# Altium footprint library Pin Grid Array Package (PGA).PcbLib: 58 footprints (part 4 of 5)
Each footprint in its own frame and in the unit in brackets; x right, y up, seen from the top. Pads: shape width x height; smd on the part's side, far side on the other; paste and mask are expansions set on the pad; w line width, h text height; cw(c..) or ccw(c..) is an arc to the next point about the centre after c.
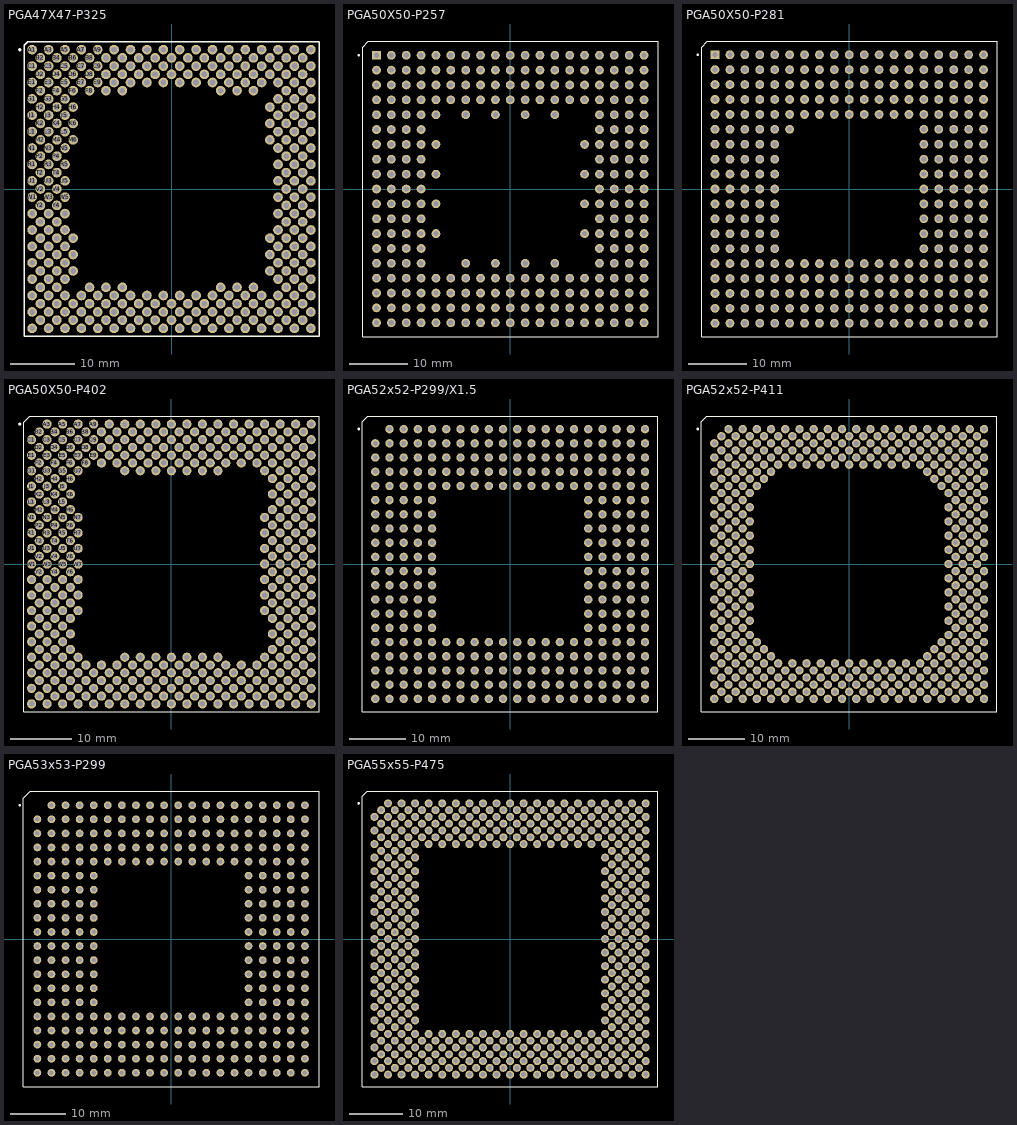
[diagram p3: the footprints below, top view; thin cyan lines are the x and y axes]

## PGA47X47-P325 [mm]
pads (325):
  round 1.5 hole 0.9: A1(-21.59,21.59) A3(-19.05,21.59) A5(-16.51,21.59) A7(-13.97,21.59) A9(-11.43,21.59) A11(-8.89,21.59) A13(-6.35,21.59) A15(-3.81,21.59) A17(-1.27,21.59) A19(1.27,21.59) A21(3.81,21.59) A23(6.35,21.59) A25(8.89,21.59) A27(11.43,21.59) A29(13.97,21.59) A31(16.51,21.59) A33(19.05,21.59) A35(21.59,21.59) AA1(-21.59,-3.81) AA3(-19.05,-3.81) AA5(-16.51,-3.81) AA31(16.51,-3.81) AA33(19.05,-3.81) AA35(21.59,-3.81) AB2(-20.32,-5.08) AB4(-17.78,-5.08) AB32(17.78,-5.08) AB34(20.32,-5.08) AC1(-21.59,-6.35) AC3(-19.05,-6.35) AC5(-16.51,-6.35) AC31(16.51,-6.35) AC33(19.05,-6.35) AC35(21.59,-6.35) AD2(-20.32,-7.62) AD4(-17.78,-7.62) AD6(-15.24,-7.62) AD30(15.24,-7.62) AD32(17.78,-7.62) AD34(20.32,-7.62) AE1(-21.59,-8.89) AE3(-19.05,-8.89) AE5(-16.51,-8.89) AE31(16.51,-8.89) AE33(19.05,-8.89) AE35(21.59,-8.89) AF2(-20.32,-10.16) AF4(-17.78,-10.16) AF6(-15.24,-10.16) AF30(15.24,-10.16) AF32(17.78,-10.16) AF34(20.32,-10.16) AG1(-21.59,-11.43) AG3(-19.05,-11.43) AG5(-16.51,-11.43) AG31(16.51,-11.43) AG33(19.05,-11.43) AG35(21.59,-11.43) AH2(-20.32,-12.7) AH4(-17.78,-12.7) AH6(-15.24,-12.7) AH30(15.24,-12.7) AH32(17.78,-12.7) AH34(20.32,-12.7) AJ1(-21.59,-13.97) AJ3(-19.05,-13.97) AJ5(-16.51,-13.97) AJ31(16.51,-13.97) AJ33(19.05,-13.97) AJ35(21.59,-13.97) AK2(-20.32,-15.24) AK4(-17.78,-15.24) AK8(-12.7,-15.24) AK10(-10.16,-15.24) AK12(-7.62,-15.24) AK24(7.62,-15.24) AK26(10.16,-15.24) AK28(12.7,-15.24) AK32(17.78,-15.24) AK34(20.32,-15.24) AL1(-21.59,-16.51) AL3(-19.05,-16.51) AL5(-16.51,-16.51) AL7(-13.97,-16.51) AL9(-11.43,-16.51) AL11(-8.89,-16.51) AL13(-6.35,-16.51) AL15(-3.81,-16.51) AL17(-1.27,-16.51) AL19(1.27,-16.51) AL21(3.81,-16.51) AL23(6.35,-16.51) AL25(8.89,-16.51) AL27(11.43,-16.51) AL29(13.97,-16.51) AL31(16.51,-16.51) AL33(19.05,-16.51) AL35(21.59,-16.51) AM2(-20.32,-17.78) AM4(-17.78,-17.78) AM6(-15.24,-17.78) AM8(-12.7,-17.78) AM10(-10.16,-17.78) AM12(-7.62,-17.78) AM14(-5.08,-17.78) AM16(-2.54,-17.78) AM18(0,-17.78) AM20(2.54,-17.78) AM22(5.08,-17.78) AM24(7.62,-17.78) AM26(10.16,-17.78) AM28(12.7,-17.78) AM30(15.24,-17.78) AM32(17.78,-17.78) AM34(20.32,-17.78) AN1(-21.59,-19.05) AN3(-19.05,-19.05) AN5(-16.51,-19.05) AN7(-13.97,-19.05) AN9(-11.43,-19.05) AN11(-8.89,-19.05) AN13(-6.35,-19.05) AN15(-3.81,-19.05) AN17(-1.27,-19.05) AN19(1.27,-19.05) AN21(3.81,-19.05) AN23(6.35,-19.05) AN25(8.89,-19.05) AN27(11.43,-19.05) AN29(13.97,-19.05) AN31(16.51,-19.05) AN33(19.05,-19.05) AN35(21.59,-19.05) AP2(-20.32,-20.32) AP4(-17.78,-20.32) AP6(-15.24,-20.32) AP8(-12.7,-20.32) AP10(-10.16,-20.32) AP12(-7.62,-20.32) AP14(-5.08,-20.32) AP16(-2.54,-20.32) AP18(0,-20.32) AP20(2.54,-20.32) AP22(5.08,-20.32) AP24(7.62,-20.32) AP26(10.16,-20.32) AP28(12.7,-20.32) AP30(15.24,-20.32) AP32(17.78,-20.32) AP34(20.32,-20.32) AR1(-21.59,-21.59) AR3(-19.05,-21.59) AR5(-16.51,-21.59) AR7(-13.97,-21.59) AR9(-11.43,-21.59) AR11(-8.89,-21.59) AR13(-6.35,-21.59) AR15(-3.81,-21.59) AR17(-1.27,-21.59) AR19(1.27,-21.59) AR21(3.81,-21.59) AR23(6.35,-21.59) AR25(8.89,-21.59) AR27(11.43,-21.59) AR29(13.97,-21.59) AR31(16.51,-21.59) AR33(19.05,-21.59) AR35(21.59,-21.59) B2(-20.32,20.32) B4(-17.78,20.32) B6(-15.24,20.32) B8(-12.7,20.32) B10(-10.16,20.32) B12(-7.62,20.32) B14(-5.08,20.32) B16(-2.54,20.32) B18(0,20.32) B20(2.54,20.32) B22(5.08,20.32) B24(7.62,20.32) B26(10.16,20.32) B28(12.7,20.32) B30(15.24,20.32) B32(17.78,20.32) B34(20.32,20.32) C1(-21.59,19.05) C3(-19.05,19.05) C5(-16.51,19.05) C7(-13.97,19.05) C9(-11.43,19.05) C11(-8.89,19.05) C13(-6.35,19.05) C15(-3.81,19.05) C17(-1.27,19.05) C19(1.27,19.05) C21(3.81,19.05) C23(6.35,19.05) C25(8.89,19.05) C27(11.43,19.05) C29(13.97,19.05) C31(16.51,19.05) C33(19.05,19.05) C35(21.59,19.05) D2(-20.32,17.78) D4(-17.78,17.78) D6(-15.24,17.78) D8(-12.7,17.78) D10(-10.16,17.78) D12(-7.62,17.78) D14(-5.08,17.78) D16(-2.54,17.78) D18(0,17.78) D20(2.54,17.78) D22(5.08,17.78) D24(7.62,17.78) D26(10.16,17.78) D28(12.7,17.78) D30(15.24,17.78) D32(17.78,17.78) D34(20.32,17.78) E1(-21.59,16.51) E3(-19.05,16.51) E5(-16.51,16.51) E7(-13.97,16.51) E9(-11.43,16.51) E11(-8.89,16.51) E13(-6.35,16.51) E15(-3.81,16.51) E17(-1.27,16.51) E19(1.27,16.51) E21(3.81,16.51) E23(6.35,16.51) E25(8.89,16.51) E27(11.43,16.51) E29(13.97,16.51) E31(16.51,16.51) E33(19.05,16.51) E35(21.59,16.51) F2(-20.32,15.24) F4(-17.78,15.24) F6(-15.24,15.24) F8(-12.7,15.24) F10(-10.16,15.24) F12(-7.62,15.24) F24(7.62,15.24) F26(10.16,15.24) F28(12.7,15.24) F32(17.78,15.24) F34(20.32,15.24) G1(-21.59,13.97) G3(-19.05,13.97) G5(-16.51,13.97) G31(16.51,13.97) G33(19.05,13.97) G35(21.59,13.97) H2(-20.32,12.7) H4(-17.78,12.7) H6(-15.24,12.7) H30(15.24,12.7) H32(17.78,12.7) H34(20.32,12.7) J1(-21.59,11.43) J3(-19.05,11.43) J5(-16.51,11.43) J31(16.51,11.43) J33(19.05,11.43) J35(21.59,11.43) K2(-20.32,10.16) K4(-17.78,10.16) K6(-15.24,10.16) K30(15.24,10.16) K32(17.78,10.16) K34(20.32,10.16) L1(-21.59,8.89) L3(-19.05,8.89) L5(-16.51,8.89) L31(16.51,8.89) L33(19.05,8.89) L35(21.59,8.89) M2(-20.32,7.62) M4(-17.78,7.62) M6(-15.24,7.62) M30(15.24,7.62) M32(17.78,7.62) M34(20.32,7.62) N1(-21.59,6.35) N3(-19.05,6.35) N5(-16.51,6.35) N31(16.51,6.35) N33(19.05,6.35) N35(21.59,6.35) P2(-20.32,5.08) P4(-17.78,5.08) P32(17.78,5.08) P34(20.32,5.08) R1(-21.59,3.81) R3(-19.05,3.81) R5(-16.51,3.81) R31(16.51,3.81) R33(19.05,3.81) R35(21.59,3.81) T2(-20.32,2.54) T4(-17.78,2.54) T32(17.78,2.54) T34(20.32,2.54) U1(-21.59,1.27) U3(-19.05,1.27) U5(-16.51,1.27) U31(16.51,1.27) U33(19.05,1.27) U35(21.59,1.27) V2(-20.32,0) V4(-17.78,0) V32(17.78,0) V34(20.32,0) W1(-21.59,-1.27) W3(-19.05,-1.27) W5(-16.51,-1.27) W31(16.51,-1.27) W33(19.05,-1.27) W35(21.59,-1.27) Y2(-20.32,-2.54) Y4(-17.78,-2.54) Y32(17.78,-2.54) Y34(20.32,-2.54)
Top Overlay:
  circle w0.25: c-23.51,21.59 r0.125
  lines w0.2: -22.86,-22.86 -22.86,22.286 -22.286,22.86 22.86,22.86 22.86,-22.86 -22.86,-22.86

## PGA50X50-P257 [mm]
pads (257):
  rect 1.5x1.5 hole 0.9: A1(-22.86,22.86)
  round 1.5 hole 0.9: A2(-20.32,22.86) A3(-17.78,22.86) A4(-15.24,22.86) A5(-12.7,22.86) A6(-10.16,22.86) A7(-7.62,22.86) A8(-5.08,22.86) A9(-2.54,22.86) A10(0,22.86) A11(2.54,22.86) A12(5.08,22.86) A13(7.62,22.86) A14(10.16,22.86) A15(12.7,22.86) A16(15.24,22.86) A17(17.78,22.86) A18(20.32,22.86) A19(22.86,22.86) B1(-22.86,20.32) B2(-20.32,20.32) B3(-17.78,20.32) B4(-15.24,20.32) B5(-12.7,20.32) B6(-10.16,20.32) B7(-7.62,20.32) B8(-5.08,20.32) B9(-2.54,20.32) B10(0,20.32) B11(2.54,20.32) B12(5.08,20.32) B13(7.62,20.32) B14(10.16,20.32) B15(12.7,20.32) B16(15.24,20.32) B17(17.78,20.32) B18(20.32,20.32) B19(22.86,20.32) C1(-22.86,17.78) C2(-20.32,17.78) C3(-17.78,17.78) C4(-15.24,17.78) C5(-12.7,17.78) C6(-10.16,17.78) C7(-7.62,17.78) C8(-5.08,17.78) C9(-2.54,17.78) C10(0,17.78) C11(2.54,17.78) C12(5.08,17.78) C13(7.62,17.78) C14(10.16,17.78) C15(12.7,17.78) C16(15.24,17.78) C17(17.78,17.78) C18(20.32,17.78) C19(22.86,17.78) D1(-22.86,15.24) D2(-20.32,15.24) D3(-17.78,15.24) D4(-15.24,15.24) D5(-12.7,15.24) D6(-10.16,15.24) D7(-7.62,15.24) D8(-5.08,15.24) D9(-2.54,15.24) D10(0,15.24) D11(2.54,15.24) D12(5.08,15.24) D13(7.62,15.24) D14(10.16,15.24) D15(12.7,15.24) D16(15.24,15.24) D17(17.78,15.24) D18(20.32,15.24) D19(22.86,15.24) E1(-22.86,12.7) E2(-20.32,12.7) E3(-17.78,12.7) E4(-15.24,12.7) E5(-12.7,12.7) E7(-7.62,12.7) E9(-2.54,12.7) E11(2.54,12.7) E13(7.62,12.7) E16(15.24,12.7) E17(17.78,12.7) E18(20.32,12.7) E19(22.86,12.7) F1(-22.86,10.16) F2(-20.32,10.16) F3(-17.78,10.16) F4(-15.24,10.16) F16(15.24,10.16) F17(17.78,10.16) F18(20.32,10.16) F19(22.86,10.16) G1(-22.86,7.62) G2(-20.32,7.62) G3(-17.78,7.62) G4(-15.24,7.62) G5(-12.7,7.62) G15(12.7,7.62) G16(15.24,7.62) G17(17.78,7.62) G18(20.32,7.62) G19(22.86,7.62) H1(-22.86,5.08) H2(-20.32,5.08) H3(-17.78,5.08) H4(-15.24,5.08) H16(15.24,5.08) H17(17.78,5.08) H18(20.32,5.08) H19(22.86,5.08) J1(-22.86,2.54) J2(-20.32,2.54) J3(-17.78,2.54) J4(-15.24,2.54) J5(-12.7,2.54) J15(12.7,2.54) J16(15.24,2.54) J17(17.78,2.54) J18(20.32,2.54) J19(22.86,2.54) K1(-22.86,0) K2(-20.32,0) K3(-17.78,0) K4(-15.24,0) K16(15.24,0) K17(17.78,0) K18(20.32,0) K19(22.86,0) L1(-22.86,-2.54) L2(-20.32,-2.54) L3(-17.78,-2.54) L4(-15.24,-2.54) L5(-12.7,-2.54) L15(12.7,-2.54) L16(15.24,-2.54) L17(17.78,-2.54) L18(20.32,-2.54) L19(22.86,-2.54) M1(-22.86,-5.08) M2(-20.32,-5.08) M3(-17.78,-5.08) M4(-15.24,-5.08) M16(15.24,-5.08) M17(17.78,-5.08) M18(20.32,-5.08) M19(22.86,-5.08) N1(-22.86,-7.62) N2(-20.32,-7.62) N3(-17.78,-7.62) N4(-15.24,-7.62) N5(-12.7,-7.62) N15(12.7,-7.62) N16(15.24,-7.62) N17(17.78,-7.62) N18(20.32,-7.62) N19(22.86,-7.62) P1(-22.86,-10.16) P2(-20.32,-10.16) P3(-17.78,-10.16) P4(-15.24,-10.16) P16(15.24,-10.16) P17(17.78,-10.16) P18(20.32,-10.16) P19(22.86,-10.16) R1(-22.86,-12.7) R2(-20.32,-12.7) R3(-17.78,-12.7) R4(-15.24,-12.7) R7(-7.62,-12.7) R9(-2.54,-12.7) R11(2.54,-12.7) R13(7.62,-12.7) R16(15.24,-12.7) R17(17.78,-12.7) R18(20.32,-12.7) R19(22.86,-12.7) T1(-22.86,-15.24) T2(-20.32,-15.24) T3(-17.78,-15.24) T4(-15.24,-15.24) T5(-12.7,-15.24) T6(-10.16,-15.24) T7(-7.62,-15.24) T8(-5.08,-15.24) T9(-2.54,-15.24) T10(0,-15.24) T11(2.54,-15.24) T12(5.08,-15.24) T13(7.62,-15.24) T14(10.16,-15.24) T15(12.7,-15.24) T16(15.24,-15.24) T17(17.78,-15.24) T18(20.32,-15.24) T19(22.86,-15.24) V1(-22.86,-17.78) V2(-20.32,-17.78) V3(-17.78,-17.78) V4(-15.24,-17.78) V5(-12.7,-17.78) V6(-10.16,-17.78) V7(-7.62,-17.78) V8(-5.08,-17.78) V9(-2.54,-17.78) V10(0,-17.78) V11(2.54,-17.78) V12(5.08,-17.78) V13(7.62,-17.78) V14(10.16,-17.78) V15(12.7,-17.78) V16(15.24,-17.78) V17(17.78,-17.78) V18(20.32,-17.78) V19(22.86,-17.78) X1(-22.86,-20.32) X2(-20.32,-20.32) X3(-17.78,-20.32) X4(-15.24,-20.32) X5(-12.7,-20.32) X6(-10.16,-20.32) X7(-7.62,-20.32) X8(-5.08,-20.32) X9(-2.54,-20.32) X10(0,-20.32) X11(2.54,-20.32) X12(5.08,-20.32) X13(7.62,-20.32) X14(10.16,-20.32) X15(12.7,-20.32) X16(15.24,-20.32) X17(17.78,-20.32) X18(20.32,-20.32) X19(22.86,-20.32) Y1(-22.86,-22.86) Y2(-20.32,-22.86) Y3(-17.78,-22.86) Y4(-15.24,-22.86) Y5(-12.7,-22.86) Y6(-10.16,-22.86) Y7(-7.62,-22.86) Y8(-5.08,-22.86) Y9(-2.54,-22.86) Y10(0,-22.86) Y11(2.54,-22.86) Y12(5.08,-22.86) Y13(7.62,-22.86) Y14(10.16,-22.86) Y15(12.7,-22.86) Y16(15.24,-22.86) Y17(17.78,-22.86) Y18(20.32,-22.86) Y19(22.86,-22.86)
Top Overlay:
  circle w0.25: c-25.9,22.86 r0.125
  lines w0.2: -25.25,-25.25 -25.25,24.25 -24.25,25.25 25.25,25.25 25.25,-25.25 -25.25,-25.25

## PGA50X50-P281 [mm]
pads (281):
  rect 1.5x1.5 hole 0.9: A1(-22.86,22.86)
  round 1.5 hole 0.9: A2(-20.32,22.86) A3(-17.78,22.86) A4(-15.24,22.86) A5(-12.7,22.86) A6(-10.16,22.86) A7(-7.62,22.86) A8(-5.08,22.86) A9(-2.54,22.86) A10(0,22.86) A11(2.54,22.86) A12(5.08,22.86) A13(7.62,22.86) A14(10.16,22.86) A15(12.7,22.86) A16(15.24,22.86) A17(17.78,22.86) A18(20.32,22.86) A19(22.86,22.86) B1(-22.86,20.32) B2(-20.32,20.32) B3(-17.78,20.32) B4(-15.24,20.32) B5(-12.7,20.32) B6(-10.16,20.32) B7(-7.62,20.32) B8(-5.08,20.32) B9(-2.54,20.32) B10(0,20.32) B11(2.54,20.32) B12(5.08,20.32) B13(7.62,20.32) B14(10.16,20.32) B15(12.7,20.32) B16(15.24,20.32) B17(17.78,20.32) B18(20.32,20.32) B19(22.86,20.32) C1(-22.86,17.78) C2(-20.32,17.78) C3(-17.78,17.78) C4(-15.24,17.78) C5(-12.7,17.78) C6(-10.16,17.78) C7(-7.62,17.78) C8(-5.08,17.78) C9(-2.54,17.78) C10(0,17.78) C11(2.54,17.78) C12(5.08,17.78) C13(7.62,17.78) C14(10.16,17.78) C15(12.7,17.78) C16(15.24,17.78) C17(17.78,17.78) C18(20.32,17.78) C19(22.86,17.78) D1(-22.86,15.24) D2(-20.32,15.24) D3(-17.78,15.24) D4(-15.24,15.24) D5(-12.7,15.24) D6(-10.16,15.24) D7(-7.62,15.24) D8(-5.08,15.24) D9(-2.54,15.24) D10(0,15.24) D11(2.54,15.24) D12(5.08,15.24) D13(7.62,15.24) D14(10.16,15.24) D15(12.7,15.24) D16(15.24,15.24) D17(17.78,15.24) D18(20.32,15.24) D19(22.86,15.24) E1(-22.86,12.7) E2(-20.32,12.7) E3(-17.78,12.7) E4(-15.24,12.7) E5(-12.7,12.7) E6(-10.16,12.7) E7(-7.62,12.7) E8(-5.08,12.7) E9(-2.54,12.7) E10(0,12.7) E11(2.54,12.7) E12(5.08,12.7) E13(7.62,12.7) E14(10.16,12.7) E15(12.7,12.7) E16(15.24,12.7) E17(17.78,12.7) E18(20.32,12.7) E19(22.86,12.7) F1(-22.86,10.16) F2(-20.32,10.16) F3(-17.78,10.16) F4(-15.24,10.16) F5(-12.7,10.16) F6(-10.16,10.16) F15(12.7,10.16) F16(15.24,10.16) F17(17.78,10.16) F18(20.32,10.16) F19(22.86,10.16) G1(-22.86,7.62) G2(-20.32,7.62) G3(-17.78,7.62) G4(-15.24,7.62) G5(-12.7,7.62) G15(12.7,7.62) G16(15.24,7.62) G17(17.78,7.62) G18(20.32,7.62) G19(22.86,7.62) H1(-22.86,5.08) H2(-20.32,5.08) H3(-17.78,5.08) H4(-15.24,5.08) H5(-12.7,5.08) H15(12.7,5.08) H16(15.24,5.08) H17(17.78,5.08) H18(20.32,5.08) H19(22.86,5.08) J1(-22.86,2.54) J2(-20.32,2.54) J3(-17.78,2.54) J4(-15.24,2.54) J5(-12.7,2.54) J15(12.7,2.54) J16(15.24,2.54) J17(17.78,2.54) J18(20.32,2.54) J19(22.86,2.54) K1(-22.86,0) K2(-20.32,0) K3(-17.78,0) K4(-15.24,0) K5(-12.7,0) K15(12.7,0) K16(15.24,0) K17(17.78,0) K18(20.32,0) K19(22.86,0) L1(-22.86,-2.54) L2(-20.32,-2.54) L3(-17.78,-2.54) L4(-15.24,-2.54) L5(-12.7,-2.54) L15(12.7,-2.54) L16(15.24,-2.54) L17(17.78,-2.54) L18(20.32,-2.54) L19(22.86,-2.54) M1(-22.86,-5.08) M2(-20.32,-5.08) M3(-17.78,-5.08) M4(-15.24,-5.08) M5(-12.7,-5.08) M15(12.7,-5.08) M16(15.24,-5.08) M17(17.78,-5.08) M18(20.32,-5.08) M19(22.86,-5.08) N1(-22.86,-7.62) N2(-20.32,-7.62) N3(-17.78,-7.62) N4(-15.24,-7.62) N5(-12.7,-7.62) N15(12.7,-7.62) N16(15.24,-7.62) N17(17.78,-7.62) N18(20.32,-7.62) N19(22.86,-7.62) P1(-22.86,-10.16) P2(-20.32,-10.16) P3(-17.78,-10.16) P4(-15.24,-10.16) P5(-12.7,-10.16) P15(12.7,-10.16) P16(15.24,-10.16) P17(17.78,-10.16) P18(20.32,-10.16) P19(22.86,-10.16) R1(-22.86,-12.7) R2(-20.32,-12.7) R3(-17.78,-12.7) R4(-15.24,-12.7) R5(-12.7,-12.7) R6(-10.16,-12.7) R7(-7.62,-12.7) R8(-5.08,-12.7) R9(-2.54,-12.7) R10(0,-12.7) R11(2.54,-12.7) R12(5.08,-12.7) R13(7.62,-12.7) R14(10.16,-12.7) R15(12.7,-12.7) R16(15.24,-12.7) R17(17.78,-12.7) R18(20.32,-12.7) R19(22.86,-12.7) T1(-22.86,-15.24) T2(-20.32,-15.24) T3(-17.78,-15.24) T4(-15.24,-15.24) T5(-12.7,-15.24) T6(-10.16,-15.24) T7(-7.62,-15.24) T8(-5.08,-15.24) T9(-2.54,-15.24) T10(0,-15.24) T11(2.54,-15.24) T12(5.08,-15.24) T13(7.62,-15.24) T14(10.16,-15.24) T15(12.7,-15.24) T16(15.24,-15.24) T17(17.78,-15.24) T18(20.32,-15.24) T19(22.86,-15.24) U1(-22.86,-17.78) U2(-20.32,-17.78) U3(-17.78,-17.78) U4(-15.24,-17.78) U5(-12.7,-17.78) U6(-10.16,-17.78) U7(-7.62,-17.78) U8(-5.08,-17.78) U9(-2.54,-17.78) U10(0,-17.78) U11(2.54,-17.78) U12(5.08,-17.78) U13(7.62,-17.78) U14(10.16,-17.78) U15(12.7,-17.78) U16(15.24,-17.78) U17(17.78,-17.78) U18(20.32,-17.78) U19(22.86,-17.78) V1(-22.86,-20.32) V2(-20.32,-20.32) V3(-17.78,-20.32) V4(-15.24,-20.32) V5(-12.7,-20.32) V6(-10.16,-20.32) V7(-7.62,-20.32) V8(-5.08,-20.32) V9(-2.54,-20.32) V10(0,-20.32) V11(2.54,-20.32) V12(5.08,-20.32) V13(7.62,-20.32) V14(10.16,-20.32) V15(12.7,-20.32) V16(15.24,-20.32) V17(17.78,-20.32) V18(20.32,-20.32) V19(22.86,-20.32) W1(-22.86,-22.86) W2(-20.32,-22.86) W3(-17.78,-22.86) W4(-15.24,-22.86) W5(-12.7,-22.86) W6(-10.16,-22.86) W7(-7.62,-22.86) W8(-5.08,-22.86) W9(-2.54,-22.86) W10(0,-22.86) W11(2.54,-22.86) W12(5.08,-22.86) W13(7.62,-22.86) W14(10.16,-22.86) W15(12.7,-22.86) W16(15.24,-22.86) W17(17.78,-22.86) W18(20.32,-22.86) W19(22.86,-22.86)
Top Overlay:
  circle w0.25: c-25.8,22.86 r0.125
  lines w0.2: -25.15,-25.15 -25.15,24.15 -24.15,25.15 25.15,25.15 25.15,-25.15 -25.15,-25.15

## PGA50X50-P402 [mm]
pads (403):
  round 1.5 hole 0.9: A3(-20.32,22.86) A5(-17.78,22.86) A7(-15.24,22.86) A9(-12.7,22.86) A11(-10.16,22.86) A13(-7.62,22.86) A15(-5.08,22.86) A17(-2.54,22.86) A19(0,22.86) A21(2.54,22.86) A23(5.08,22.86) A25(7.62,22.86) A27(10.16,22.86) A29(12.7,22.86) A31(15.24,22.86) A33(17.78,22.86) A35(20.32,22.86) A37(22.86,22.86) AA1(-22.86,-2.54) AA3(-20.32,-2.54) AA5(-17.78,-2.54) AA7(-15.24,-2.54) AA31(15.24,-2.54) AA33(17.78,-2.54) AA35(20.32,-2.54) AA37(22.86,-2.54) AB2(-21.59,-3.81) AB4(-19.05,-3.81) AB6(-16.51,-3.81) AB32(16.51,-3.81) AB34(19.05,-3.81) AB36(21.59,-3.81) AC1(-22.86,-5.08) AC3(-20.32,-5.08) AC5(-17.78,-5.08) AC7(-15.24,-5.08) AC31(15.24,-5.08) AC33(17.78,-5.08) AC35(20.32,-5.08) AC37(22.86,-5.08) AD2(-21.59,-6.35) AD4(-19.05,-6.35) AD6(-16.51,-6.35) AD32(16.51,-6.35) AD34(19.05,-6.35) AD36(21.59,-6.35) AE1(-22.86,-7.62) AE3(-20.32,-7.62) AE5(-17.78,-7.62) AE7(-15.24,-7.62) AE31(15.24,-7.62) AE33(17.78,-7.62) AE35(20.32,-7.62) AE37(22.86,-7.62) AF2(-21.59,-8.89) AF4(-19.05,-8.89) AF6(-16.51,-8.89) AF32(16.51,-8.89) AF34(19.05,-8.89) AF36(21.59,-8.89) AG1(-22.86,-10.16) AG3(-20.32,-10.16) AG5(-17.78,-10.16) AG33(17.78,-10.16) AG35(20.32,-10.16) AG37(22.86,-10.16) AH2(-21.59,-11.43) AH4(-19.05,-11.43) AH6(-16.51,-11.43) AH32(16.51,-11.43) AH34(19.05,-11.43) AH36(21.59,-11.43) AJ1(-22.86,-12.7) AJ3(-20.32,-12.7) AJ5(-17.78,-12.7) AJ33(17.78,-12.7) AJ35(20.32,-12.7) AJ37(22.86,-12.7) AK2(-21.59,-13.97) AK4(-19.05,-13.97) AK6(-16.51,-13.97) AK32(16.51,-13.97) AK34(19.05,-13.97) AK36(21.59,-13.97) AL1(-22.86,-15.24) AL3(-20.32,-15.24) AL5(-17.78,-15.24) AL7(-15.24,-15.24) AL13(-7.62,-15.24) AL15(-5.08,-15.24) AL17(-2.54,-15.24) AL19(0,-15.24) AL21(2.54,-15.24) AL23(5.08,-15.24) AL25(7.62,-15.24) AL31(15.24,-15.24) AL33(17.78,-15.24) AL35(20.32,-15.24) AL37(22.86,-15.24) AM2(-21.59,-16.51) AM4(-19.05,-16.51) AM6(-16.51,-16.51) AM8(-13.97,-16.51) AM10(-11.43,-16.51) AM12(-8.89,-16.51) AM14(-6.35,-16.51) AM16(-3.81,-16.51) AM18(-1.27,-16.51) AM20(1.27,-16.51) AM22(3.81,-16.51) AM24(6.35,-16.51) AM26(8.89,-16.51) AM28(11.43,-16.51) AM30(13.97,-16.51) AM32(16.51,-16.51) AM34(19.05,-16.51) AM36(21.59,-16.51) AN1(-22.86,-17.78) AN3(-20.32,-17.78) AN5(-17.78,-17.78) AN7(-15.24,-17.78) AN9(-12.7,-17.78) AN11(-10.16,-17.78) AN13(-7.62,-17.78) AN15(-5.08,-17.78) AN17(-2.54,-17.78) AN19(0,-17.78) AN21(2.54,-17.78) AN23(5.08,-17.78) AN25(7.62,-17.78) AN27(10.16,-17.78) AN29(12.7,-17.78) AN31(15.24,-17.78) AN33(17.78,-17.78) AN35(20.32,-17.78) AN37(22.86,-17.78) AP2(-21.59,-19.05) AP4(-19.05,-19.05) AP6(-16.51,-19.05) AP8(-13.97,-19.05) AP10(-11.43,-19.05) AP12(-8.89,-19.05) AP14(-6.35,-19.05) AP16(-3.81,-19.05) AP18(-1.27,-19.05) AP20(1.27,-19.05) AP22(3.81,-19.05) AP24(6.35,-19.05) AP26(8.89,-19.05) AP28(11.43,-19.05) AP30(13.97,-19.05) AP32(16.51,-19.05) AP34(19.05,-19.05) AP36(21.59,-19.05) AR1(-22.86,-20.32) AR3(-20.32,-20.32) AR5(-17.78,-20.32) AR7(-15.24,-20.32) AR9(-12.7,-20.32) AR11(-10.16,-20.32) AR13(-7.62,-20.32) AR15(-5.08,-20.32) AR17(-2.54,-20.32) AR19(0,-20.32) AR21(2.54,-20.32) AR23(5.08,-20.32) AR25(7.62,-20.32) AR27(10.16,-20.32) AR29(12.7,-20.32) AR31(15.24,-20.32) AR33(17.78,-20.32) AR35(20.32,-20.32) AR37(22.86,-20.32) AT2(-21.59,-21.59) AT4(-19.05,-21.59) AT6(-16.51,-21.59) AT8(-13.97,-21.59) AT10(-11.43,-21.59) AT12(-8.89,-21.59) AT14(-6.35,-21.59) AT16(-3.81,-21.59) AT18(-1.27,-21.59) AT20(1.27,-21.59) AT22(3.81,-21.59) AT24(6.35,-21.59) AT26(8.89,-21.59) AT28(11.43,-21.59) AT30(13.97,-21.59) AT32(16.51,-21.59) AT34(19.05,-21.59) AT36(21.59,-21.59) AU1(-22.86,-22.86) AU3(-20.32,-22.86) AU5(-17.78,-22.86) AU7(-15.24,-22.86) AU9(-12.7,-22.86) AU11(-10.16,-22.86) AU13(-7.62,-22.86) AU15(-5.08,-22.86) AU17(-2.54,-22.86) AU19(0,-22.86) AU21(2.54,-22.86) AU23(5.08,-22.86) AU25(7.62,-22.86) AU27(10.16,-22.86) AU29(12.7,-22.86) AU31(15.24,-22.86) AU33(17.78,-22.86) AU35(20.32,-22.86) AU37(22.86,-22.86) B2(-21.59,21.59) B4(-19.05,21.59) B6(-16.51,21.59) B8(-13.97,21.59) B10(-11.43,21.59) B12(-8.89,21.59) B14(-6.35,21.59) B16(-3.81,21.59) B18(-1.27,21.59) B20(1.27,21.59) B22(3.81,21.59) B24(6.35,21.59) B26(8.89,21.59) B28(11.43,21.59) B30(13.97,21.59) B32(16.51,21.59) B34(19.05,21.59) B36(21.59,21.59) C1(-22.86,20.32) C3(-20.32,20.32) C5(-17.78,20.32) C7(-15.24,20.32) C9(-12.7,20.32) C11(-10.16,20.32) C13(-7.62,20.32) C15(-5.08,20.32) C17(-2.54,20.32) C19(0,20.32) C21(2.54,20.32) C23(5.08,20.32) C25(7.62,20.32) C27(10.16,20.32) C29(12.7,20.32) C31(15.24,20.32) C33(17.78,20.32) C35(20.32,20.32) C37(22.86,20.32) D2(-21.59,19.05) D4(-19.05,19.05) D6(-16.51,19.05) D8(-13.97,19.05) D10(-11.43,19.05) D12(-8.89,19.05) D14(-6.35,19.05) D16(-3.81,19.05) D18(-1.27,19.05) D20(1.27,19.05) D22(3.81,19.05) D24(6.35,19.05) D26(8.89,19.05) D28(11.43,19.05) D30(13.97,19.05) D32(16.51,19.05) D34(19.05,19.05) D36(21.59,19.05) E1(-22.86,17.78) E3(-20.32,17.78) E5(-17.78,17.78) E7(-15.24,17.78) E9(-12.7,17.78) E11(-10.16,17.78) E13(-7.62,17.78) E15(-5.08,17.78) E17(-2.54,17.78) E19(0,17.78) E21(2.54,17.78) E23(5.08,17.78) E25(7.62,17.78) E27(10.16,17.78) E29(12.7,17.78) E31(15.24,17.78) E33(17.78,17.78) E35(20.32,17.78) E37(22.86,17.78) F2(-21.59,16.51) F4(-19.05,16.51) F6(-16.51,16.51) F8(-13.97,16.51) F10(-11.43,16.51) F12(-8.89,16.51) F14(-6.35,16.51) F16(-3.81,16.51) F18(-1.27,16.51) F20(1.27,16.51) F22(3.81,16.51) F24(6.35,16.51) F26(8.89,16.51) F28(11.43,16.51) F30(13.97,16.51) F32(16.51,16.51) F34(19.05,16.51) F36(21.59,16.51) G1(-22.86,15.24) G3(-20.32,15.24) G5(-17.78,15.24) G7(-15.24,15.24) G13(-7.62,15.24) G15(-5.08,15.24) G17(-2.54,15.24) G19(0,15.24) G21(2.54,15.24) G23(5.08,15.24) G25(7.62,15.24) G31(15.24,15.24) G33(17.78,15.24) G35(20.32,15.24) G37(22.86,15.24) H2(-21.59,13.97) H4(-19.05,13.97) H6(-16.51,13.97) H32(16.51,13.97) H34(19.05,13.97) H36(21.59,13.97) J1(-22.86,12.7) J3(-20.32,12.7) J5(-17.78,12.7) J33(17.78,12.7) J35(20.32,12.7) J37(22.86,12.7) K2(-21.59,11.43) K4(-19.05,11.43) K6(-16.51,11.43) K32(16.51,11.43) K34(19.05,11.43) K36(21.59,11.43) L1(-22.86,10.16) L3(-20.32,10.16) L5(-17.78,10.16) L33(17.78,10.16) L35(20.32,10.16) L37(22.86,10.16) M2(-21.59,8.89) M4(-19.05,8.89) M6(-16.51,8.89) M32(16.51,8.89) M34(19.05,8.89) M36(21.59,8.89) N1(-22.86,7.62) N3(-20.32,7.62) N5(-17.78,7.62) N7(-15.24,7.62) N31(15.24,7.62) N33(17.78,7.62) N35(20.32,7.62) N37(22.86,7.62) P2(-21.59,6.35) P4(-19.05,6.35) P6(-16.51,6.35) P32(16.51,6.35) P34(19.05,6.35) P36(21.59,6.35) R1(-22.86,5.08) R3(-20.32,5.08) R5(-17.78,5.08) R7(-15.24,5.08) R31(15.24,5.08) R33(17.78,5.08) R35(20.32,5.08) R37(22.86,5.08) T2(-21.59,3.81) T4(-19.05,3.81) T6(-16.51,3.81) T32(16.51,3.81) T34(19.05,3.81) T36(21.59,3.81) U1(-22.86,2.54) U3(-20.32,2.54) U5(-17.78,2.54) U7(-15.24,2.54) U31(15.24,2.54) U33(17.78,2.54) U35(20.32,2.54) U37(22.86,2.54) V2(-21.59,1.27) V4(-19.05,1.27) V6(-16.51,1.27) V32(16.51,1.27) V34(19.05,1.27) V36(21.59,1.27) W1(-22.86,0) W3(-20.32,0) W5(-17.78,0) W7(-15.24,0) W31(15.24,0) W33(17.78,0) W35(20.32,0) W37(22.86,0) Y2(-21.59,-1.27) Y4(-19.05,-1.27) Y6(-16.51,-1.27) Y32(16.51,-1.27) Y34(19.05,-1.27) Y36(21.59,-1.27)
Top Overlay:
  circle w0.25: c-24.78,22.86 r0.125
  lines w0.2: -24.13,-24.13 24.13,-24.13 24.13,24.13 -23.13,24.13 -24.13,23.13 -24.13,-24.13

## PGA52x52-P299/X1.5 [mm]
pads (299):
  round 1.5 hole 0.9: A2(-21.59,24.13) A3(-19.05,24.13) A4(-16.51,24.13) A5(-13.97,24.13) A6(-11.43,24.13) A7(-8.89,24.13) A8(-6.35,24.13) A9(-3.81,24.13) A10(-1.27,24.13) A11(1.27,24.13) A12(3.81,24.13) A13(6.35,24.13) A14(8.89,24.13) A15(11.43,24.13) A16(13.97,24.13) A17(16.51,24.13) A18(19.05,24.13) A19(21.59,24.13) A20(24.13,24.13) B1(-24.13,21.59) B2(-21.59,21.59) B3(-19.05,21.59) B4(-16.51,21.59) B5(-13.97,21.59) B6(-11.43,21.59) B7(-8.89,21.59) B8(-6.35,21.59) B9(-3.81,21.59) B10(-1.27,21.59) B11(1.27,21.59) B12(3.81,21.59) B13(6.35,21.59) B14(8.89,21.59) B15(11.43,21.59) B16(13.97,21.59) B17(16.51,21.59) B18(19.05,21.59) B19(21.59,21.59) B20(24.13,21.59) C1(-24.13,19.05) C2(-21.59,19.05) C3(-19.05,19.05) C4(-16.51,19.05) C5(-13.97,19.05) C6(-11.43,19.05) C7(-8.89,19.05) C8(-6.35,19.05) C9(-3.81,19.05) C10(-1.27,19.05) C11(1.27,19.05) C12(3.81,19.05) C13(6.35,19.05) C14(8.89,19.05) C15(11.43,19.05) C16(13.97,19.05) C17(16.51,19.05) C18(19.05,19.05) C19(21.59,19.05) C20(24.13,19.05) D1(-24.13,16.51) D2(-21.59,16.51) D3(-19.05,16.51) D4(-16.51,16.51) D5(-13.97,16.51) D6(-11.43,16.51) D7(-8.89,16.51) D8(-6.35,16.51) D9(-3.81,16.51) D10(-1.27,16.51) D11(1.27,16.51) D12(3.81,16.51) D13(6.35,16.51) D14(8.89,16.51) D15(11.43,16.51) D16(13.97,16.51) D17(16.51,16.51) D18(19.05,16.51) D19(21.59,16.51) D20(24.13,16.51) E1(-24.13,13.97) E2(-21.59,13.97) E3(-19.05,13.97) E4(-16.51,13.97) E5(-13.97,13.97) E6(-11.43,13.97) E7(-8.89,13.97) E8(-6.35,13.97) E9(-3.81,13.97) E10(-1.27,13.97) E11(1.27,13.97) E12(3.81,13.97) E13(6.35,13.97) E14(8.89,13.97) E15(11.43,13.97) E16(13.97,13.97) E17(16.51,13.97) E18(19.05,13.97) E19(21.59,13.97) E20(24.13,13.97) F1(-24.13,11.43) F2(-21.59,11.43) F3(-19.05,11.43) F4(-16.51,11.43) F5(-13.97,11.43) F16(13.97,11.43) F17(16.51,11.43) F18(19.05,11.43) F19(21.59,11.43) F20(24.13,11.43) G1(-24.13,8.89) G2(-21.59,8.89) G3(-19.05,8.89) G4(-16.51,8.89) G5(-13.97,8.89) G16(13.97,8.89) G17(16.51,8.89) G18(19.05,8.89) G19(21.59,8.89) G20(24.13,8.89) H1(-24.13,6.35) H2(-21.59,6.35) H3(-19.05,6.35) H4(-16.51,6.35) H5(-13.97,6.35) H16(13.97,6.35) H17(16.51,6.35) H18(19.05,6.35) H19(21.59,6.35) H20(24.13,6.35) J1(-24.13,3.81) J2(-21.59,3.81) J3(-19.05,3.81) J4(-16.51,3.81) J5(-13.97,3.81) J16(13.97,3.81) J17(16.51,3.81) J18(19.05,3.81) J19(21.59,3.81) J20(24.13,3.81) K1(-24.13,1.27) K2(-21.59,1.27) K3(-19.05,1.27) K4(-16.51,1.27) K5(-13.97,1.27) K16(13.97,1.27) K17(16.51,1.27) K18(19.05,1.27) K19(21.59,1.27) K20(24.13,1.27) L1(-24.13,-1.27) L2(-21.59,-1.27) L3(-19.05,-1.27) L4(-16.51,-1.27) L5(-13.97,-1.27) L16(13.97,-1.27) L17(16.51,-1.27) L18(19.05,-1.27) L19(21.59,-1.27) L20(24.13,-1.27) M1(-24.13,-3.81) M2(-21.59,-3.81) M3(-19.05,-3.81) M4(-16.51,-3.81) M5(-13.97,-3.81) M16(13.97,-3.81) M17(16.51,-3.81) M18(19.05,-3.81) M19(21.59,-3.81) M20(24.13,-3.81) N1(-24.13,-6.35) N2(-21.59,-6.35) N3(-19.05,-6.35) N4(-16.51,-6.35) N5(-13.97,-6.35) N16(13.97,-6.35) N17(16.51,-6.35) N18(19.05,-6.35) N19(21.59,-6.35) N20(24.13,-6.35) P1(-24.13,-8.89) P2(-21.59,-8.89) P3(-19.05,-8.89) P4(-16.51,-8.89) P5(-13.97,-8.89) P16(13.97,-8.89) P17(16.51,-8.89) P18(19.05,-8.89) P19(21.59,-8.89) P20(24.13,-8.89) R1(-24.13,-11.43) R2(-21.59,-11.43) R3(-19.05,-11.43) R4(-16.51,-11.43) R5(-13.97,-11.43) R16(13.97,-11.43) R17(16.51,-11.43) R18(19.05,-11.43) R19(21.59,-11.43) R20(24.13,-11.43) T1(-24.13,-13.97) T2(-21.59,-13.97) T3(-19.05,-13.97) T4(-16.51,-13.97) T5(-13.97,-13.97) T6(-11.43,-13.97) T7(-8.89,-13.97) T8(-6.35,-13.97) T9(-3.81,-13.97) T10(-1.27,-13.97) T11(1.27,-13.97) T12(3.81,-13.97) T13(6.35,-13.97) T14(8.89,-13.97) T15(11.43,-13.97) T16(13.97,-13.97) T17(16.51,-13.97) T18(19.05,-13.97) T19(21.59,-13.97) T20(24.13,-13.97) U1(-24.13,-16.51) U2(-21.59,-16.51) U3(-19.05,-16.51) U4(-16.51,-16.51) U5(-13.97,-16.51) U6(-11.43,-16.51) U7(-8.89,-16.51) U8(-6.35,-16.51) U9(-3.81,-16.51) U10(-1.27,-16.51) U11(1.27,-16.51) U12(3.81,-16.51) U13(6.35,-16.51) U14(8.89,-16.51) U15(11.43,-16.51) U16(13.97,-16.51) U17(16.51,-16.51) U18(19.05,-16.51) U19(21.59,-16.51) U20(24.13,-16.51) V1(-24.13,-19.05) V2(-21.59,-19.05) V3(-19.05,-19.05) V4(-16.51,-19.05) V5(-13.97,-19.05) V6(-11.43,-19.05) V7(-8.89,-19.05) V8(-6.35,-19.05) V9(-3.81,-19.05) V10(-1.27,-19.05) V11(1.27,-19.05) V12(3.81,-19.05) V13(6.35,-19.05) V14(8.89,-19.05) V15(11.43,-19.05) V16(13.97,-19.05) V17(16.51,-19.05) V18(19.05,-19.05) V19(21.59,-19.05) V20(24.13,-19.05) W1(-24.13,-21.59) W2(-21.59,-21.59) W3(-19.05,-21.59) W4(-16.51,-21.59) W5(-13.97,-21.59) W6(-11.43,-21.59) W7(-8.89,-21.59) W8(-6.35,-21.59) W9(-3.81,-21.59) W10(-1.27,-21.59) W11(1.27,-21.59) W12(3.81,-21.59) W13(6.35,-21.59) W14(8.89,-21.59) W15(11.43,-21.59) W16(13.97,-21.59) W17(16.51,-21.59) W18(19.05,-21.59) W19(21.59,-21.59) W20(24.13,-21.59) Y1(-24.13,-24.13) Y2(-21.59,-24.13) Y3(-19.05,-24.13) Y4(-16.51,-24.13) Y5(-13.97,-24.13) Y6(-11.43,-24.13) Y7(-8.89,-24.13) Y8(-6.35,-24.13) Y9(-3.81,-24.13) Y10(-1.27,-24.13) Y11(1.27,-24.13) Y12(3.81,-24.13) Y13(6.35,-24.13) Y14(8.89,-24.13) Y15(11.43,-24.13) Y16(13.97,-24.13) Y17(16.51,-24.13) Y18(19.05,-24.13) Y19(21.59,-24.13) Y20(24.13,-24.13)
Top Overlay:
  circle w0.25: c-27.1,24.13 r0.125
  lines w0.2: -26.45,-26.45 26.45,-26.45 26.45,26.45 -25.45,26.45 -26.45,25.45 -26.45,-26.45

## PGA52x52-P411 [mm]
pads (411):
  round 1.5 hole 0.9: A3(-21.59,24.13) A5(-19.05,24.13) A7(-16.51,24.13) A9(-13.97,24.13) A11(-11.43,24.13) A13(-8.89,24.13) A15(-6.35,24.13) A17(-3.81,24.13) A19(-1.27,24.13) A21(1.27,24.13) A23(3.81,24.13) A25(6.35,24.13) A27(8.89,24.13) A29(11.43,24.13) A31(13.97,24.13) A33(16.51,24.13) A35(19.05,24.13) A37(21.59,24.13) A39(24.13,24.13) AA1(-24.13,-1.27) AA3(-21.59,-1.27) AA5(-19.05,-1.27) AA35(19.05,-1.27) AA37(21.59,-1.27) AA39(24.13,-1.27) AB2(-22.86,-2.54) AB4(-20.32,-2.54) AB6(-17.78,-2.54) AB34(17.78,-2.54) AB36(20.32,-2.54) AB38(22.86,-2.54) AC1(-24.13,-3.81) AC3(-21.59,-3.81) AC5(-19.05,-3.81) AC35(19.05,-3.81) AC37(21.59,-3.81) AC39(24.13,-3.81) AD2(-22.86,-5.08) AD4(-20.32,-5.08) AD6(-17.78,-5.08) AD34(17.78,-5.08) AD36(20.32,-5.08) AD38(22.86,-5.08) AE1(-24.13,-6.35) AE3(-21.59,-6.35) AE5(-19.05,-6.35) AE35(19.05,-6.35) AE37(21.59,-6.35) AE39(24.13,-6.35) AF2(-22.86,-7.62) AF4(-20.32,-7.62) AF6(-17.78,-7.62) AF34(17.78,-7.62) AF36(20.32,-7.62) AF38(22.86,-7.62) AG1(-24.13,-8.89) AG3(-21.59,-8.89) AG5(-19.05,-8.89) AG35(19.05,-8.89) AG37(21.59,-8.89) AG39(24.13,-8.89) AH2(-22.86,-10.16) AH4(-20.32,-10.16) AH6(-17.78,-10.16) AH34(17.78,-10.16) AH36(20.32,-10.16) AH38(22.86,-10.16) AJ1(-24.13,-11.43) AJ3(-21.59,-11.43) AJ5(-19.05,-11.43) AJ35(19.05,-11.43) AJ37(21.59,-11.43) AJ39(24.13,-11.43) AK2(-22.86,-12.7) AK4(-20.32,-12.7) AK6(-17.78,-12.7) AK34(17.78,-12.7) AK36(20.32,-12.7) AK38(22.86,-12.7) AL1(-24.13,-13.97) AL3(-21.59,-13.97) AL5(-19.05,-13.97) AL7(-16.51,-13.97) AL33(16.51,-13.97) AL35(19.05,-13.97) AL37(21.59,-13.97) AL39(24.13,-13.97) AM2(-22.86,-15.24) AM4(-20.32,-15.24) AM6(-17.78,-15.24) AM8(-15.24,-15.24) AM32(15.24,-15.24) AM34(17.78,-15.24) AM36(20.32,-15.24) AM38(22.86,-15.24) AN1(-24.13,-16.51) AN3(-21.59,-16.51) AN5(-19.05,-16.51) AN7(-16.51,-16.51) AN9(-13.97,-16.51) AN31(13.97,-16.51) AN33(16.51,-16.51) AN35(19.05,-16.51) AN37(21.59,-16.51) AN39(24.13,-16.51) AP2(-22.86,-17.78) AP4(-20.32,-17.78) AP6(-17.78,-17.78) AP8(-15.24,-17.78) AP10(-12.7,-17.78) AP12(-10.16,-17.78) AP14(-7.62,-17.78) AP16(-5.08,-17.78) AP18(-2.54,-17.78) AP20(0,-17.78) AP22(2.54,-17.78) AP24(5.08,-17.78) AP26(7.62,-17.78) AP28(10.16,-17.78) AP30(12.7,-17.78) AP32(15.24,-17.78) AP34(17.78,-17.78) AP36(20.32,-17.78) AP38(22.86,-17.78) AR1(-24.13,-19.05) AR3(-21.59,-19.05) AR5(-19.05,-19.05) AR7(-16.51,-19.05) AR9(-13.97,-19.05) AR11(-11.43,-19.05) AR13(-8.89,-19.05) AR15(-6.35,-19.05) AR17(-3.81,-19.05) AR19(-1.27,-19.05) AR21(1.27,-19.05) AR23(3.81,-19.05) AR25(6.35,-19.05) AR27(8.89,-19.05) AR29(11.43,-19.05) AR31(13.97,-19.05) AR33(16.51,-19.05) AR35(19.05,-19.05) AR37(21.59,-19.05) AR39(24.13,-19.05) AT2(-22.86,-20.32) AT4(-20.32,-20.32) AT6(-17.78,-20.32) AT8(-15.24,-20.32) AT10(-12.7,-20.32) AT12(-10.16,-20.32) AT14(-7.62,-20.32) AT16(-5.08,-20.32) AT18(-2.54,-20.32) AT20(0,-20.32) AT22(2.54,-20.32) AT24(5.08,-20.32) AT26(7.62,-20.32) AT28(10.16,-20.32) AT30(12.7,-20.32) AT32(15.24,-20.32) AT34(17.78,-20.32) AT36(20.32,-20.32) AT38(22.86,-20.32) AU1(-24.13,-21.59) AU3(-21.59,-21.59) AU5(-19.05,-21.59) AU7(-16.51,-21.59) AU9(-13.97,-21.59) AU11(-11.43,-21.59) AU13(-8.89,-21.59) AU15(-6.35,-21.59) AU17(-3.81,-21.59) AU19(-1.27,-21.59) AU21(1.27,-21.59) AU23(3.81,-21.59) AU25(6.35,-21.59) AU27(8.89,-21.59) AU29(11.43,-21.59) AU31(13.97,-21.59) AU33(16.51,-21.59) AU35(19.05,-21.59) AU37(21.59,-21.59) AU39(24.13,-21.59) AV2(-22.86,-22.86) AV4(-20.32,-22.86) AV6(-17.78,-22.86) AV8(-15.24,-22.86) AV10(-12.7,-22.86) AV12(-10.16,-22.86) AV14(-7.62,-22.86) AV16(-5.08,-22.86) AV18(-2.54,-22.86) AV20(0,-22.86) AV22(2.54,-22.86) AV24(5.08,-22.86) AV26(7.62,-22.86) AV28(10.16,-22.86) AV30(12.7,-22.86) AV32(15.24,-22.86) AV34(17.78,-22.86) AV36(20.32,-22.86) AV38(22.86,-22.86) AW1(-24.13,-24.13) AW3(-21.59,-24.13) AW5(-19.05,-24.13) AW7(-16.51,-24.13) AW9(-13.97,-24.13) AW11(-11.43,-24.13) AW13(-8.89,-24.13) AW15(-6.35,-24.13) AW17(-3.81,-24.13) AW19(-1.27,-24.13) AW21(1.27,-24.13) AW23(3.81,-24.13) AW25(6.35,-24.13) AW27(8.89,-24.13) AW29(11.43,-24.13) AW31(13.97,-24.13) AW33(16.51,-24.13) AW35(19.05,-24.13) AW37(21.59,-24.13) AW39(24.13,-24.13) B2(-22.86,22.86) B4(-20.32,22.86) B6(-17.78,22.86) B8(-15.24,22.86) B10(-12.7,22.86) B12(-10.16,22.86) B14(-7.62,22.86) B16(-5.08,22.86) B18(-2.54,22.86) B20(0,22.86) B22(2.54,22.86) B24(5.08,22.86) B26(7.62,22.86) B28(10.16,22.86) B30(12.7,22.86) B32(15.24,22.86) B34(17.78,22.86) B36(20.32,22.86) B38(22.86,22.86) C1(-24.13,21.59) C3(-21.59,21.59) C5(-19.05,21.59) C7(-16.51,21.59) C9(-13.97,21.59) C11(-11.43,21.59) C13(-8.89,21.59) C15(-6.35,21.59) C17(-3.81,21.59) C19(-1.27,21.59) C21(1.27,21.59) C23(3.81,21.59) C25(6.35,21.59) C27(8.89,21.59) C29(11.43,21.59) C31(13.97,21.59) C33(16.51,21.59) C35(19.05,21.59) C37(21.59,21.59) C39(24.13,21.59) D2(-22.86,20.32) D4(-20.32,20.32) D6(-17.78,20.32) D8(-15.24,20.32) D10(-12.7,20.32) D12(-10.16,20.32) D14(-7.62,20.32) D16(-5.08,20.32) D18(-2.54,20.32) D20(0,20.32) D22(2.54,20.32) D24(5.08,20.32) D26(7.62,20.32) D28(10.16,20.32) D30(12.7,20.32) D32(15.24,20.32) D34(17.78,20.32) D36(20.32,20.32) D38(22.86,20.32) E1(-24.13,19.05) E3(-21.59,19.05) E5(-19.05,19.05) E7(-16.51,19.05) E9(-13.97,19.05) E11(-11.43,19.05) E13(-8.89,19.05) E15(-6.35,19.05) E17(-3.81,19.05) E19(-1.27,19.05) E21(1.27,19.05) E23(3.81,19.05) E25(6.35,19.05) E27(8.89,19.05) E29(11.43,19.05) E31(13.97,19.05) E33(16.51,19.05) E35(19.05,19.05) E37(21.59,19.05) E39(24.13,19.05) F2(-22.86,17.78) F4(-20.32,17.78) F6(-17.78,17.78) F8(-15.24,17.78) F10(-12.7,17.78) F12(-10.16,17.78) F14(-7.62,17.78) F16(-5.08,17.78) F18(-2.54,17.78) F20(0,17.78) F22(2.54,17.78) F24(5.08,17.78) F26(7.62,17.78) F28(10.16,17.78) F30(12.7,17.78) F32(15.24,17.78) F34(17.78,17.78) F36(20.32,17.78) F38(22.86,17.78) G1(-24.13,16.51) G3(-21.59,16.51) G5(-19.05,16.51) G7(-16.51,16.51) G9(-13.97,16.51) G31(13.97,16.51) G33(16.51,16.51) G35(19.05,16.51) G37(21.59,16.51) G39(24.13,16.51) H2(-22.86,15.24) H4(-20.32,15.24) H6(-17.78,15.24) H8(-15.24,15.24) H32(15.24,15.24) H34(17.78,15.24) H36(20.32,15.24) H38(22.86,15.24) J1(-24.13,13.97) J3(-21.59,13.97) J5(-19.05,13.97) J7(-16.51,13.97) J33(16.51,13.97) J35(19.05,13.97) J37(21.59,13.97) J39(24.13,13.97) K2(-22.86,12.7) K4(-20.32,12.7) K6(-17.78,12.7) K34(17.78,12.7) K36(20.32,12.7) K38(22.86,12.7) L1(-24.13,11.43) L3(-21.59,11.43) L5(-19.05,11.43) L35(19.05,11.43) L37(21.59,11.43) L39(24.13,11.43) M2(-22.86,10.16) M4(-20.32,10.16) M6(-17.78,10.16) M34(17.78,10.16) M36(20.32,10.16) M38(22.86,10.16) N1(-24.13,8.89) N3(-21.59,8.89) N5(-19.05,8.89) N35(19.05,8.89) N37(21.59,8.89) N39(24.13,8.89) P2(-22.86,7.62) P4(-20.32,7.62) P6(-17.78,7.62) P34(17.78,7.62) P36(20.32,7.62) P38(22.86,7.62) R1(-24.13,6.35) R3(-21.59,6.35) R5(-19.05,6.35) R35(19.05,6.35) R37(21.59,6.35) R39(24.13,6.35) T2(-22.86,5.08) T4(-20.32,5.08) T6(-17.78,5.08) T34(17.78,5.08) T36(20.32,5.08) T38(22.86,5.08) U1(-24.13,3.81) U3(-21.59,3.81) U5(-19.05,3.81) U35(19.05,3.81) U37(21.59,3.81) U39(24.13,3.81) V2(-22.86,2.54) V4(-20.32,2.54) V6(-17.78,2.54) V34(17.78,2.54) V36(20.32,2.54) V38(22.86,2.54) W1(-24.13,1.27) W3(-21.59,1.27) W5(-19.05,1.27) W35(19.05,1.27) W37(21.59,1.27) W39(24.13,1.27) Y2(-22.86,0) Y4(-20.32,0) Y6(-17.78,0) Y34(17.78,0) Y36(20.32,0) Y38(22.86,0)
Top Overlay:
  circle w0.25: c-27.1,24.13 r0.125
  lines w0.2: -26.45,-26.45 -26.45,25.45 -25.45,26.45 26.45,26.45 26.45,-26.45 -26.45,-26.45

## PGA53x53-P299 [mm]
pads (299):
  round 1.4 hole 0.8: A2(-21.59,24.13) A3(-19.05,24.13) A4(-16.51,24.13) A5(-13.97,24.13) A6(-11.43,24.13) A7(-8.89,24.13) A8(-6.35,24.13) A9(-3.81,24.13) A10(-1.27,24.13) A11(1.27,24.13) A12(3.81,24.13) A13(6.35,24.13) A14(8.89,24.13) A15(11.43,24.13) A16(13.97,24.13) A17(16.51,24.13) A18(19.05,24.13) A19(21.59,24.13) A20(24.13,24.13) B1(-24.13,21.59) B2(-21.59,21.59) B3(-19.05,21.59) B4(-16.51,21.59) B5(-13.97,21.59) B6(-11.43,21.59) B7(-8.89,21.59) B8(-6.35,21.59) B9(-3.81,21.59) B10(-1.27,21.59) B11(1.27,21.59) B12(3.81,21.59) B13(6.35,21.59) B14(8.89,21.59) B15(11.43,21.59) B16(13.97,21.59) B17(16.51,21.59) B18(19.05,21.59) B19(21.59,21.59) B20(24.13,21.59) C1(-24.13,19.05) C2(-21.59,19.05) C3(-19.05,19.05) C4(-16.51,19.05) C5(-13.97,19.05) C6(-11.43,19.05) C7(-8.89,19.05) C8(-6.35,19.05) C9(-3.81,19.05) C10(-1.27,19.05) C11(1.27,19.05) C12(3.81,19.05) C13(6.35,19.05) C14(8.89,19.05) C15(11.43,19.05) C16(13.97,19.05) C17(16.51,19.05) C18(19.05,19.05) C19(21.59,19.05) C20(24.13,19.05) D1(-24.13,16.51) D2(-21.59,16.51) D3(-19.05,16.51) D4(-16.51,16.51) D5(-13.97,16.51) D6(-11.43,16.51) D7(-8.89,16.51) D8(-6.35,16.51) D9(-3.81,16.51) D10(-1.27,16.51) D11(1.27,16.51) D12(3.81,16.51) D13(6.35,16.51) D14(8.89,16.51) D15(11.43,16.51) D16(13.97,16.51) D17(16.51,16.51) D18(19.05,16.51) D19(21.59,16.51) D20(24.13,16.51) E1(-24.13,13.97) E2(-21.59,13.97) E3(-19.05,13.97) E4(-16.51,13.97) E5(-13.97,13.97) E6(-11.43,13.97) E7(-8.89,13.97) E8(-6.35,13.97) E9(-3.81,13.97) E10(-1.27,13.97) E11(1.27,13.97) E12(3.81,13.97) E13(6.35,13.97) E14(8.89,13.97) E15(11.43,13.97) E16(13.97,13.97) E17(16.51,13.97) E18(19.05,13.97) E19(21.59,13.97) E20(24.13,13.97) F1(-24.13,11.43) F2(-21.59,11.43) F3(-19.05,11.43) F4(-16.51,11.43) F5(-13.97,11.43) F16(13.97,11.43) F17(16.51,11.43) F18(19.05,11.43) F19(21.59,11.43) F20(24.13,11.43) G1(-24.13,8.89) G2(-21.59,8.89) G3(-19.05,8.89) G4(-16.51,8.89) G5(-13.97,8.89) G16(13.97,8.89) G17(16.51,8.89) G18(19.05,8.89) G19(21.59,8.89) G20(24.13,8.89) H1(-24.13,6.35) H2(-21.59,6.35) H3(-19.05,6.35) H4(-16.51,6.35) H5(-13.97,6.35) H16(13.97,6.35) H17(16.51,6.35) H18(19.05,6.35) H19(21.59,6.35) H20(24.13,6.35) J1(-24.13,3.81) J2(-21.59,3.81) J3(-19.05,3.81) J4(-16.51,3.81) J5(-13.97,3.81) J16(13.97,3.81) J17(16.51,3.81) J18(19.05,3.81) J19(21.59,3.81) J20(24.13,3.81) K1(-24.13,1.27) K2(-21.59,1.27) K3(-19.05,1.27) K4(-16.51,1.27) K5(-13.97,1.27) K16(13.97,1.27) K17(16.51,1.27) K18(19.05,1.27) K19(21.59,1.27) K20(24.13,1.27) L1(-24.13,-1.27) L2(-21.59,-1.27) L3(-19.05,-1.27) L4(-16.51,-1.27) L5(-13.97,-1.27) L16(13.97,-1.27) L17(16.51,-1.27) L18(19.05,-1.27) L19(21.59,-1.27) L20(24.13,-1.27) M1(-24.13,-3.81) M2(-21.59,-3.81) M3(-19.05,-3.81) M4(-16.51,-3.81) M5(-13.97,-3.81) M16(13.97,-3.81) M17(16.51,-3.81) M18(19.05,-3.81) M19(21.59,-3.81) M20(24.13,-3.81) N1(-24.13,-6.35) N2(-21.59,-6.35) N3(-19.05,-6.35) N4(-16.51,-6.35) N5(-13.97,-6.35) N16(13.97,-6.35) N17(16.51,-6.35) N18(19.05,-6.35) N19(21.59,-6.35) N20(24.13,-6.35) P1(-24.13,-8.89) P2(-21.59,-8.89) P3(-19.05,-8.89) P4(-16.51,-8.89) P5(-13.97,-8.89) P16(13.97,-8.89) P17(16.51,-8.89) P18(19.05,-8.89) P19(21.59,-8.89) P20(24.13,-8.89) R1(-24.13,-11.43) R2(-21.59,-11.43) R3(-19.05,-11.43) R4(-16.51,-11.43) R5(-13.97,-11.43) R16(13.97,-11.43) R17(16.51,-11.43) R18(19.05,-11.43) R19(21.59,-11.43) R20(24.13,-11.43) T1(-24.13,-13.97) T2(-21.59,-13.97) T3(-19.05,-13.97) T4(-16.51,-13.97) T5(-13.97,-13.97) T6(-11.43,-13.97) T7(-8.89,-13.97) T8(-6.35,-13.97) T9(-3.81,-13.97) T10(-1.27,-13.97) T11(1.27,-13.97) T12(3.81,-13.97) T13(6.35,-13.97) T14(8.89,-13.97) T15(11.43,-13.97) T16(13.97,-13.97) T17(16.51,-13.97) T18(19.05,-13.97) T19(21.59,-13.97) T20(24.13,-13.97) U1(-24.13,-16.51) U2(-21.59,-16.51) U3(-19.05,-16.51) U4(-16.51,-16.51) U5(-13.97,-16.51) U6(-11.43,-16.51) U7(-8.89,-16.51) U8(-6.35,-16.51) U9(-3.81,-16.51) U10(-1.27,-16.51) U11(1.27,-16.51) U12(3.81,-16.51) U13(6.35,-16.51) U14(8.89,-16.51) U15(11.43,-16.51) U16(13.97,-16.51) U17(16.51,-16.51) U18(19.05,-16.51) U19(21.59,-16.51) U20(24.13,-16.51) V1(-24.13,-19.05) V2(-21.59,-19.05) V3(-19.05,-19.05) V4(-16.51,-19.05) V5(-13.97,-19.05) V6(-11.43,-19.05) V7(-8.89,-19.05) V8(-6.35,-19.05) V9(-3.81,-19.05) V10(-1.27,-19.05) V11(1.27,-19.05) V12(3.81,-19.05) V13(6.35,-19.05) V14(8.89,-19.05) V15(11.43,-19.05) V16(13.97,-19.05) V17(16.51,-19.05) V18(19.05,-19.05) V19(21.59,-19.05) V20(24.13,-19.05) W1(-24.13,-21.59) W2(-21.59,-21.59) W3(-19.05,-21.59) W4(-16.51,-21.59) W5(-13.97,-21.59) W6(-11.43,-21.59) W7(-8.89,-21.59) W8(-6.35,-21.59) W9(-3.81,-21.59) W10(-1.27,-21.59) W11(1.27,-21.59) W12(3.81,-21.59) W13(6.35,-21.59) W14(8.89,-21.59) W15(11.43,-21.59) W16(13.97,-21.59) W17(16.51,-21.59) W18(19.05,-21.59) W19(21.59,-21.59) W20(24.13,-21.59) Y1(-24.13,-24.13) Y2(-21.59,-24.13) Y3(-19.05,-24.13) Y4(-16.51,-24.13) Y5(-13.97,-24.13) Y6(-11.43,-24.13) Y7(-8.89,-24.13) Y8(-6.35,-24.13) Y9(-3.81,-24.13) Y10(-1.27,-24.13) Y11(1.27,-24.13) Y12(3.81,-24.13) Y13(6.35,-24.13) Y14(8.89,-24.13) Y15(11.43,-24.13) Y16(13.97,-24.13) Y17(16.51,-24.13) Y18(19.05,-24.13) Y19(21.59,-24.13) Y20(24.13,-24.13)
Top Overlay:
  circle w0.25: c-27.32,24.13 r0.125
  lines w0.2: -26.67,-26.67 -26.67,25.4 -25.4,26.67 26.67,26.67 26.67,-26.67 -26.67,-26.67

## PGA55x55-P475 [mm]
pads (475):
  round 1.5 hole 0.9: A3(-22.86,25.4) A5(-20.32,25.4) A7(-17.78,25.4) A9(-15.24,25.4) A11(-12.7,25.4) A13(-10.16,25.4) A15(-7.62,25.4) A17(-5.08,25.4) A19(-2.54,25.4) A21(0,25.4) A23(2.54,25.4) A25(5.08,25.4) A27(7.62,25.4) A29(10.16,25.4) A31(12.7,25.4) A33(15.24,25.4) A35(17.78,25.4) A37(20.32,25.4) A39(22.86,25.4) A41(25.4,25.4) AA1(-25.4,0) AA3(-22.86,0) AA5(-20.32,0) AA7(-17.78,0) AA35(17.78,0) AA37(20.32,0) AA39(22.86,0) AA41(25.4,0) AB2(-24.13,-1.27) AB4(-21.59,-1.27) AB6(-19.05,-1.27) AB36(19.05,-1.27) AB38(21.59,-1.27) AB40(24.13,-1.27) AC1(-25.4,-2.54) AC3(-22.86,-2.54) AC5(-20.32,-2.54) AC7(-17.78,-2.54) AC35(17.78,-2.54) AC37(20.32,-2.54) AC39(22.86,-2.54) AC41(25.4,-2.54) AD2(-24.13,-3.81) AD4(-21.59,-3.81) AD6(-19.05,-3.81) AD36(19.05,-3.81) AD38(21.59,-3.81) AD40(24.13,-3.81) AE1(-25.4,-5.08) AE3(-22.86,-5.08) AE5(-20.32,-5.08) AE7(-17.78,-5.08) AE35(17.78,-5.08) AE37(20.32,-5.08) AE39(22.86,-5.08) AE41(25.4,-5.08) AF2(-24.13,-6.35) AF4(-21.59,-6.35) AF6(-19.05,-6.35) AF36(19.05,-6.35) AF38(21.59,-6.35) AF40(24.13,-6.35) AG1(-25.4,-7.62) AG3(-22.86,-7.62) AG5(-20.32,-7.62) AG7(-17.78,-7.62) AG35(17.78,-7.62) AG37(20.32,-7.62) AG39(22.86,-7.62) AG41(25.4,-7.62) AH2(-24.13,-8.89) AH4(-21.59,-8.89) AH6(-19.05,-8.89) AH36(19.05,-8.89) AH38(21.59,-8.89) AH40(24.13,-8.89) AJ1(-25.4,-10.16) AJ3(-22.86,-10.16) AJ5(-20.32,-10.16) AJ7(-17.78,-10.16) AJ35(17.78,-10.16) AJ37(20.32,-10.16) AJ39(22.86,-10.16) AJ41(25.4,-10.16) AK2(-24.13,-11.43) AK4(-21.59,-11.43) AK6(-19.05,-11.43) AK36(19.05,-11.43) AK38(21.59,-11.43) AK40(24.13,-11.43) AL1(-25.4,-12.7) AL3(-22.86,-12.7) AL5(-20.32,-12.7) AL7(-17.78,-12.7) AL35(17.78,-12.7) AL37(20.32,-12.7) AL39(22.86,-12.7) AL41(25.4,-12.7) AM2(-24.13,-13.97) AM4(-21.59,-13.97) AM6(-19.05,-13.97) AM36(19.05,-13.97) AM38(21.59,-13.97) AM40(24.13,-13.97) AN1(-25.4,-15.24) AN3(-22.86,-15.24) AN5(-20.32,-15.24) AN7(-17.78,-15.24) AN35(17.78,-15.24) AN37(20.32,-15.24) AN39(22.86,-15.24) AN41(25.4,-15.24) AP2(-24.13,-16.51) AP4(-21.59,-16.51) AP6(-19.05,-16.51) AP36(19.05,-16.51) AP38(21.59,-16.51) AP40(24.13,-16.51) AR1(-25.4,-17.78) AR3(-22.86,-17.78) AR5(-20.32,-17.78) AR7(-17.78,-17.78) AR9(-15.24,-17.78) AR11(-12.7,-17.78) AR13(-10.16,-17.78) AR15(-7.62,-17.78) AR17(-5.08,-17.78) AR19(-2.54,-17.78) AR21(0,-17.78) AR23(2.54,-17.78) AR25(5.08,-17.78) AR27(7.62,-17.78) AR29(10.16,-17.78) AR31(12.7,-17.78) AR33(15.24,-17.78) AR35(17.78,-17.78) AR37(20.32,-17.78) AR39(22.86,-17.78) AR41(25.4,-17.78) AT2(-24.13,-19.05) AT4(-21.59,-19.05) AT6(-19.05,-19.05) AT8(-16.51,-19.05) AT10(-13.97,-19.05) AT12(-11.43,-19.05) AT14(-8.89,-19.05) AT16(-6.35,-19.05) AT18(-3.81,-19.05) AT20(-1.27,-19.05) AT22(1.27,-19.05) AT24(3.81,-19.05) AT26(6.35,-19.05) AT28(8.89,-19.05) AT30(11.43,-19.05) AT32(13.97,-19.05) AT34(16.51,-19.05) AT36(19.05,-19.05) AT38(21.59,-19.05) AT40(24.13,-19.05) AU1(-25.4,-20.32) AU3(-22.86,-20.32) AU5(-20.32,-20.32) AU7(-17.78,-20.32) AU9(-15.24,-20.32) AU11(-12.7,-20.32) AU13(-10.16,-20.32) AU15(-7.62,-20.32) AU17(-5.08,-20.32) AU19(-2.54,-20.32) AU21(0,-20.32) AU23(2.54,-20.32) AU25(5.08,-20.32) AU27(7.62,-20.32) AU29(10.16,-20.32) AU31(12.7,-20.32) AU33(15.24,-20.32) AU35(17.78,-20.32) AU37(20.32,-20.32) AU39(22.86,-20.32) AU41(25.4,-20.32) AV2(-24.13,-21.59) AV4(-21.59,-21.59) AV6(-19.05,-21.59) AV8(-16.51,-21.59) AV10(-13.97,-21.59) AV12(-11.43,-21.59) AV14(-8.89,-21.59) AV16(-6.35,-21.59) AV18(-3.81,-21.59) AV20(-1.27,-21.59) AV22(1.27,-21.59) AV24(3.81,-21.59) AV26(6.35,-21.59) AV28(8.89,-21.59) AV30(11.43,-21.59) AV32(13.97,-21.59) AV34(16.51,-21.59) AV36(19.05,-21.59) AV38(21.59,-21.59) AV40(24.13,-21.59) AW1(-25.4,-22.86) AW3(-22.86,-22.86) AW5(-20.32,-22.86) AW7(-17.78,-22.86) AW9(-15.24,-22.86) AW11(-12.7,-22.86) AW13(-10.16,-22.86) AW15(-7.62,-22.86) AW17(-5.08,-22.86) AW19(-2.54,-22.86) AW21(0,-22.86) AW23(2.54,-22.86) AW25(5.08,-22.86) AW27(7.62,-22.86) AW29(10.16,-22.86) AW31(12.7,-22.86) AW33(15.24,-22.86) AW35(17.78,-22.86) AW37(20.32,-22.86) AW39(22.86,-22.86) AW41(25.4,-22.86) AY2(-24.13,-24.13) AY4(-21.59,-24.13) AY6(-19.05,-24.13) AY8(-16.51,-24.13) AY10(-13.97,-24.13) AY12(-11.43,-24.13) AY14(-8.89,-24.13) AY16(-6.35,-24.13) AY18(-3.81,-24.13) AY20(-1.27,-24.13) AY22(1.27,-24.13) AY24(3.81,-24.13) AY26(6.35,-24.13) AY28(8.89,-24.13) AY30(11.43,-24.13) AY32(13.97,-24.13) AY34(16.51,-24.13) AY36(19.05,-24.13) AY38(21.59,-24.13) AY40(24.13,-24.13) B2(-24.13,24.13) B4(-21.59,24.13) B6(-19.05,24.13) B8(-16.51,24.13) B10(-13.97,24.13) B12(-11.43,24.13) B14(-8.89,24.13) B16(-6.35,24.13) B18(-3.81,24.13) B20(-1.27,24.13) B22(1.27,24.13) B24(3.81,24.13) B26(6.35,24.13) B28(8.89,24.13) B30(11.43,24.13) B32(13.97,24.13) B34(16.51,24.13) B36(19.05,24.13) B38(21.59,24.13) B40(24.13,24.13) BA1(-25.4,-25.4) BA3(-22.86,-25.4) BA5(-20.32,-25.4) BA7(-17.78,-25.4) BA9(-15.24,-25.4) BA11(-12.7,-25.4) BA13(-10.16,-25.4) BA15(-7.62,-25.4) BA17(-5.08,-25.4) BA19(-2.54,-25.4) BA21(0,-25.4) BA23(2.54,-25.4) BA25(5.08,-25.4) BA27(7.62,-25.4) BA29(10.16,-25.4) BA31(12.7,-25.4) BA33(15.24,-25.4) BA35(17.78,-25.4) BA37(20.32,-25.4) BA39(22.86,-25.4) BA41(25.4,-25.4) C1(-25.4,22.86) C3(-22.86,22.86) C5(-20.32,22.86) C7(-17.78,22.86) C9(-15.24,22.86) C11(-12.7,22.86) C13(-10.16,22.86) C15(-7.62,22.86) C17(-5.08,22.86) C19(-2.54,22.86) C21(0,22.86) C23(2.54,22.86) C25(5.08,22.86) C27(7.62,22.86) C29(10.16,22.86) C31(12.7,22.86) C33(15.24,22.86) C35(17.78,22.86) C37(20.32,22.86) C39(22.86,22.86) C41(25.4,22.86) D2(-24.13,21.59) D4(-21.59,21.59) D6(-19.05,21.59) D8(-16.51,21.59) D10(-13.97,21.59) D12(-11.43,21.59) D14(-8.89,21.59) D16(-6.35,21.59) D18(-3.81,21.59) D20(-1.27,21.59) D22(1.27,21.59) D24(3.81,21.59) D26(6.35,21.59) D28(8.89,21.59) D30(11.43,21.59) D32(13.97,21.59) D34(16.51,21.59) D36(19.05,21.59) D38(21.59,21.59) D40(24.13,21.59) E1(-25.4,20.32) E3(-22.86,20.32) E5(-20.32,20.32) E7(-17.78,20.32) E9(-15.24,20.32) E11(-12.7,20.32) E13(-10.16,20.32) E15(-7.62,20.32) E17(-5.08,20.32) E19(-2.54,20.32) E21(0,20.32) E23(2.54,20.32) E25(5.08,20.32) E27(7.62,20.32) E29(10.16,20.32) E31(12.7,20.32) E33(15.24,20.32) E35(17.78,20.32) E37(20.32,20.32) E39(22.86,20.32) E41(25.4,20.32) F2(-24.13,19.05) F4(-21.59,19.05) F6(-19.05,19.05) F8(-16.51,19.05) F10(-13.97,19.05) F12(-11.43,19.05) F14(-8.89,19.05) F16(-6.35,19.05) F18(-3.81,19.05) F20(-1.27,19.05) F22(1.27,19.05) F24(3.81,19.05) F26(6.35,19.05) F28(8.89,19.05) F30(11.43,19.05) F32(13.97,19.05) F34(16.51,19.05) F36(19.05,19.05) F38(21.59,19.05) F40(24.13,19.05) G1(-25.4,17.78) G3(-22.86,17.78) G5(-20.32,17.78) G7(-17.78,17.78) G9(-15.24,17.78) G11(-12.7,17.78) G13(-10.16,17.78) G15(-7.62,17.78) G17(-5.08,17.78) G19(-2.54,17.78) G21(0,17.78) G23(2.54,17.78) G25(5.08,17.78) G27(7.62,17.78) G29(10.16,17.78) G31(12.7,17.78) G33(15.24,17.78) G35(17.78,17.78) G37(20.32,17.78) G39(22.86,17.78) G41(25.4,17.78) H2(-24.13,16.51) H4(-21.59,16.51) H6(-19.05,16.51) H36(19.05,16.51) H38(21.59,16.51) H40(24.13,16.51) J1(-25.4,15.24) J3(-22.86,15.24) J5(-20.32,15.24) J7(-17.78,15.24) J35(17.78,15.24) J37(20.32,15.24) J39(22.86,15.24) J41(25.4,15.24) K2(-24.13,13.97) K4(-21.59,13.97) K6(-19.05,13.97) K36(19.05,13.97) K38(21.59,13.97) K40(24.13,13.97) L1(-25.4,12.7) L3(-22.86,12.7) L5(-20.32,12.7) L7(-17.78,12.7) L35(17.78,12.7) L37(20.32,12.7) L39(22.86,12.7) L41(25.4,12.7) M2(-24.13,11.43) M4(-21.59,11.43) M6(-19.05,11.43) M36(19.05,11.43) M38(21.59,11.43) M40(24.13,11.43) N1(-25.4,10.16) N3(-22.86,10.16) N5(-20.32,10.16) N7(-17.78,10.16) N35(17.78,10.16) N37(20.32,10.16) N39(22.86,10.16) N41(25.4,10.16) P2(-24.13,8.89) P4(-21.59,8.89) P6(-19.05,8.89) P36(19.05,8.89) P38(21.59,8.89) P40(24.13,8.89) R1(-25.4,7.62) R3(-22.86,7.62) R5(-20.32,7.62) R7(-17.78,7.62) R35(17.78,7.62) R37(20.32,7.62) R39(22.86,7.62) R41(25.4,7.62) T2(-24.13,6.35) T4(-21.59,6.35) T6(-19.05,6.35) T36(19.05,6.35) T38(21.59,6.35) T40(24.13,6.35) U1(-25.4,5.08) U3(-22.86,5.08) U5(-20.32,5.08) U7(-17.78,5.08) U35(17.78,5.08) U37(20.32,5.08) U39(22.86,5.08) U41(25.4,5.08) V2(-24.13,3.81) V4(-21.59,3.81) V6(-19.05,3.81) V36(19.05,3.81) V38(21.59,3.81) V40(24.13,3.81) W1(-25.4,2.54) W3(-22.86,2.54) W5(-20.32,2.54) W7(-17.78,2.54) W35(17.78,2.54) W37(20.32,2.54) W39(22.86,2.54) W41(25.4,2.54) Y2(-24.13,1.27) Y4(-21.59,1.27) Y6(-19.05,1.27) Y36(19.05,1.27) Y38(21.59,1.27) Y40(24.13,1.27)
Top Overlay:
  circle w0.25: c-28.35,25.4 r0.125
  lines w0.2: -27.7,-27.7 -27.7,26.7 -26.7,27.7 27.7,27.7 27.7,-27.7 -27.7,-27.7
